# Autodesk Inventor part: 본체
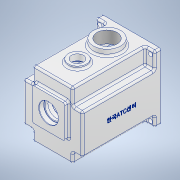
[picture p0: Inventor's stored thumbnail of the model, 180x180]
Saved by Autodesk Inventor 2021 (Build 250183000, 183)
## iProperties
Created: 2022-08
Part Number: 본체
Material: 알루미늄 6061
Document SubType Name: Modeling
Designer: Owner
Mass: 1399.43 g
Surface Area: 1169.88 cm^2
Volume: 518.309 cm^3
Density: 2.7 g/cm^3
Appearance: 알루미늄 - 평지
Author: Owner
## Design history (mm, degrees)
sketch "스케치1"
  geometry: L1 (-49, 55)-(49, 55); L2 (49, 55)-(49, -55); L3 (49, -55)-(-49, -55); L4 (-49, -55)-(-49, 55); L5 (-49, 55)-(49, -55); L6 (49, 55)-(-49, -55); 3 further points
  constraints: 12 end point, 3 midpoint, 2 parallel, 1 coincident, 1 horizontal, 1 perpendicular
  dimensions: "d0" = 98 distance of L2.end L3.end; "d1" = 110 distance of L1.end L2.end
extrude "돌출1" new body sketch "스케치1" stored distance "d2" = 130; taper "d3" = 0 deg
sketch "스케치4"
  geometry: L1 (49, 55)-(-49, 55) reference; L2 (49, 55)-(33, 55); L3 (33, 55)-(33, 28); L4 (33, 28)-(49, 28); L5 (49, 28)-(49, 55); L6 (-49, 55)-(-33, 55); L7 (-33, 55)-(-33, 28); L8 (-33, 28)-(-49, 28); L9 (-49, 28)-(-49, 55); L10 (-49, -55)-(-33, -55); L11 (-33, -55)-(-33, -38); L12 (-33, -38)-(-49, -38); L13 (-49, -38)-(-49, -55); L14 (49, -55)-(33, -55); L15 (33, -55)-(33, -38); L16 (33, -38)-(49, -38); L17 (49, -38)-(49, -55); 4 further points
  constraints: 32 end point, 8 parallel, 4 horizontal, 4 perpendicular, 1 coincident
  dimensions: "d6" = 16 distance of L3.end L4.end; "d7" = 16 distance of L7.end L8.end; "d8" = 27 distance of L2.end L3.end; "d9" = 27 distance of L6.end L7.end; "d10" = 17 distance of L10.end L11.end; "d11" = 16 distance of L11.end L12.end; "d12" = 16 distance of L15.end L16.end; "d13" = 17 distance of L14.end L15.end
extrude "돌출2" cut sketch "스케치4" distance "d14" = 120; taper "d15" = 0 deg
sketch "스케치5"
  geometry: L1 (33, 55)-(-33, 55) reference; L2 (-27, 33)-(27, 33); L3 (27, 33)-(27, -21); L4 (27, -21)-(-27, -21); L5 (-27, -21)-(-27, 33); L6 (-27, 33)-(27, -21); L7 (27, 33)-(-27, -21); L8 (-33, -55)-(33, -55) reference; 3 further points
  constraints: 12 end point, 3 midpoint, 2 parallel, 1 horizontal, 1 perpendicular, 1 vertical alignment
  dimensions: "d146" = 54 distance of L2.start L2.end; "d147" = 54 distance of L2.end L3.end; "d148" = 61 distance from line of L8 point (0, 6)
extrude "돌출3" join sketch "스케치5" distance "d19" = 7; taper "d20" = 0 deg
sketch "스케치6"
  geometry: L1 (-33, -55)-(33, -55) reference; 2 further points
  constraints: 1 vertical alignment
  dimensions: "d151" = 61 distance from line of L1 point (0, 6)
sketch "스케치7"
  geometry: L1 (-23, 45)-(23, 45); L2 (23, 45)-(23, 30.143); L3 (23, 10.468)-(-23, 10.468); L4 (-23, 30.143)-(-23, 45); L5 (-49, -55)-(49, -55) reference; L6 (-36, 4)-(-41.809, 4); L7 (-36, -4)-(-41.809, -4); L8 (36, 4)-(41.809, 4); L9 (36, -4)-(41.809, -4); A1 r 4 centre (-36, 0) between (-36, -4) and (-36, 4); A2 r 4 centre (36, 0) between (36, 4) and (36, -4); A3 r 42 centre (0, -5) between (-23, 30.143) and (23, 30.143); 2 further points
  constraints: 16 end point, 6 point on circle, 5 horizontal, 4 tangent, 3 centre point, 2 horizontal alignment, 2 parallel, 2 vertical alignment, 1 midpoint, 1 perpendicular
  dimensions: "d22" = 46 distance of L3.start L3.end; "d23" = 100 distance between parallel lines of L5 L1; "d26" = 8 diameter of A1; "d27" = 36 distance of point (0, 0) A1.centre; "d28" = 8 diameter of A2; "d29" = 36 distance of A2.centre point (0, 0); "d30" = 46 distance of L1.start L1.end; "d189" = 84 diameter of A3; "d190" = 50 distance from line of A3.centre L5
extrude "돌출4" cut sketch "스케치7" distance "d24" = 121; taper "d25" = 0 deg
sketch "스케치8"
  geometry: L1 (-49, -55)-(49, -55) reference; C1 r 21 at (0, 6); 1 further point
  constraints: 1 centre point, 1 vertical alignment
  dimensions: "d149" = 42 diameter of C1; "d150" = 61 distance from line of L1 C1.centre
extrude "돌출5" join sketch "스케치8" distance "d33" = 7; taper "d34" = 0 deg
sketch "스케치9"
  geometry: L1 (-26, 48)-(26, 48); L2 (26, 48)-(26, 31.729); L3 (-26, 31.729)-(-26, 48); L4 (-49, -55)-(49, -55) reference; A1 r 45 centre (0, -5) between (-26, 31.729) and (26, 31.729); 3 further points
  constraints: 6 end point, 2 point on circle, 2 vertical alignment, 1 centre point, 1 horizontal, 1 midpoint, 1 parallel, 1 perpendicular, 1 point on line
  dimensions: "d36" = 52 distance of L1.start L1.end; "d37" = 103 distance from line of L4 point (0, 48); "d187" = 90 diameter of A1; "d188" = 50 distance from line of A1.centre L4
extrude "돌출6" cut sketch "스케치9" distance "d38" = 9; taper "d39" = 0 deg
hole "구멍1" sketch "스케치6" diameter "d40" = 28; stored, may be unused: countersink angle "d44" = 90 deg, drill point angle "d46" = 0 deg; dims "d41" = 6, "d42" = 32, "d43" = 8.3, "d45" = 100000
chamfer "모따기1" distance "d54" = 0.8; stored, may be unused: second distance "d55" = 2, angle "d56" = 30 deg
fillet "모깎기1" dims "d57" = 0.3
sketch "스케치13"
  geometry: L1 (-49, -55)-(49, -55) reference; A1 r 15 centre (0, -25) between (-8.978, -12.984) and (8.978, -12.984); A2 r 21 centre (0, 6) between (8.978, -12.984) and (-8.978, -12.984) reference; 3 further points
  constraints: 4 point on circle, 1 centre point, 1 vertical alignment
  dimensions: "d153" = 30 diameter of A1; "d169" = 30 distance from line of L1 A1.centre
extrude "돌출7" join sketch "스케치13" distance "d80" = 7; taper "d81" = 0 deg
sketch "스케치16"
  geometry: L1 (0, 0)-(98, 0) reference; C1 r 15 at (49, -89); 1 further point
  constraints: 1 centre point, 1 vertical alignment
  dimensions: "d93" = 30 diameter of C1; "d94" = 89 distance from line of L1 C1.centre
extrude "돌출9" join sketch "스케치16" distance "d95" = 5; taper "d96" = 0 deg
sketch "스케치17"
  geometry: L1 (0, 0)-(98, 0) reference; C1 r 22.5 at (49, -40); 1 further point
  constraints: 1 centre point, 1 vertical alignment
  dimensions: "d97" = 45 diameter of C1; "d98" = 40 distance from line of L1 C1.centre
extrude "돌출10" join sketch "스케치17" distance "d99" = 10; taper "d100" = 0 deg
sketch "스케치18"
  geometry: C1 r 15 at (23, -32) reference; 2 further points
  constraints: 1 coincident
hole "구멍6" sketch "스케치18" at (23, -32) diameter "d101" = 20; stored, may be unused: countersink angle "d105" = 90 deg, drill point angle "d107" = 0 deg; dims "d102" = 7, "d103" = 30, "d104" = 5, "d106" = 7
fillet "모깎기3" dims "d115" = 3
sketch "스케치20"
  geometry: L1 (46, 55)-(-46, 55) reference; L2 (49, -52)-(49, 52) reference; 2 further points
  dimensions: "d116" = 7 distance from line of L1 point (42, 48); "d117" = 7 distance from line of L2 point (42, 48)
hole "구멍8" sketch "스케치20" at (42, 48) diameter "d118" = 7; stored, may be unused: countersink angle "d122" = 90 deg, drill point angle "d124" = 0 deg; dims "d119" = 70, "d120" = 30, "d121" = 5, "d123" = 77.3
fillet "모깎기4" dims "d125" = 3
fillet "모깎기5" dims "d126" = 3
fillet "모깎기6" dims "d127" = 3
fillet "모깎기7" dims "d128" = 3
fillet "모깎기9" dims "d130" = 3
fillet "모깎기10" dims "d131" = 3
fillet "모깎기11" dims "d135" = 3
chamfer "모따기4" distance "d139" = 1; stored, may be unused: second distance "d140" = 2, angle "d141" = 30 deg
sketch "스케치21"
  geometry: L1 (-130, 104)-(-130, 83) reference; L2 (-13, 107)-(-127, 107) reference; 2 further points
  constraints: 1 other
  dimensions: "d142" = 65 distance from line of L1 point (-65, 47); "d143" = 60 distance from line of point (-65, 47) L2
feature "엠보싱1" sketch "스케치21" dims "d144" = 0.5, "d145" = 0
sketch "스케치22"
  geometry: A1 r 21 centre (0, 6) between (8.978, -12.984) and (-8.978, -12.984) reference; 2 further points
  constraints: 1 coincident
hole "구멍9" sketch "스케치22" at (0, 6) diameter "d155" = 35; stored, may be unused: countersink angle "d159" = 90 deg, drill point angle "d161" = 0 deg; dims "d156" = 70, "d157" = 30, "d158" = 5, "d160" = 10
sketch "스케치23"
  geometry: A1 r 15 centre (0, -25) between (-8.978, -12.984) and (8.978, -12.984) reference; 2 further points
  constraints: 1 coincident
hole "구멍10" sketch "스케치23" at (0, -25) diameter "d162" = 22; stored, may be unused: countersink angle "d166" = 90 deg, drill point angle "d168" = 0 deg; dims "d163" = 70, "d164" = 30, "d165" = 5, "d167" = 7
chamfer "모따기5" distance "d170" = 1; stored, may be unused: second distance "d171" = 2, angle "d172" = 30 deg
fillet "모깎기12" dims "d173" = 3
fillet "모깎기13" dims "d174" = 3
sketch "스케치24"
  geometry: C1 r 9.5 at (0, 0); C2 r 11 at (0, 0) reference; 1 further point
  constraints: 1 centre point, 1 concentric
  dimensions: "d175" = 19 diameter of C1
extrude "돌출11" cut sketch "스케치24" distance "d176" = 3; taper "d177" = 0 deg
fillet "모깎기14" dims "d178" = 3
fillet "모깎기15" dims "d179" = 3
sketch "스케치26"
  geometry: L1 (-46, -55)-(46, -55) reference; L2 (-36, -1)-(-41.809, -1); L3 (-36, -9)-(-41.809, -9); A1 r 4 centre (-36, -5) between (-36, -9) and (-36, -1); A2 r 42 centre (0, -5) between (-23, 30.143) and (23, 30.143) reference; 1 further point
  constraints: 4 end point, 4 point on circle, 2 horizontal, 2 tangent, 1 centre point
  dimensions: "d191" = 8 diameter of A1; "d192" = 50 distance from line of L1 A1.centre; "d193" = 36 horizontal distance of point (0, 0) A1.centre
extrude "돌출12" join sketch "스케치26" distance "d194" = 121; taper "d195" = 0 deg
sketch "스케치27"
  geometry: A1 r 4 centre (-36, -5) between (-36, -9) and (-36, -1) reference; 2 further points
  constraints: 1 coincident
hole "구멍12" sketch "스케치27" at (-36, -5) diameter "d196" = 3.242; stored, may be unused: countersink angle "d200" = 90 deg, drill point angle "d202" = 118 deg; dims "d197" = 7, "d198" = 30, "d199" = 5, "d201" = 9
fillet "모깎기16" dims "d203" = 3
fillet "모깎기17" dims "d204" = 3
fillet "모깎기18" dims "d205" = 3
chamfer "모따기6" distance "d206" = 1; stored, may be unused: second distance "d207" = 2, angle "d208" = 30 deg
sketch "스케치28"
  geometry: C1 r 22.5 at (0, 0) reference; 2 further points
  constraints: 1 coincident
hole "구멍13" sketch "스케치28" at (0, 0) diameter "d209" = 33.376; stored, may be unused: countersink angle "d213" = 90 deg, drill point angle "d215" = 0 deg; dims "d210" = 70, "d211" = 30, "d212" = 5, "d214" = 77.3
fillet "모깎기19" dims "d216" = 0.3
node "솔리드1"
mirror "미러2"
mirror "미러3"
mirror "미러4"
feature "A9D066F2-1C7D-4E18-AEED-F7BC21143FA4" dims "d40" = 28, "d41" = 6, "d42" = 32, "d43" = 8.3, "d44" = 90 deg, "d45" = 100000, "d46" = 0
